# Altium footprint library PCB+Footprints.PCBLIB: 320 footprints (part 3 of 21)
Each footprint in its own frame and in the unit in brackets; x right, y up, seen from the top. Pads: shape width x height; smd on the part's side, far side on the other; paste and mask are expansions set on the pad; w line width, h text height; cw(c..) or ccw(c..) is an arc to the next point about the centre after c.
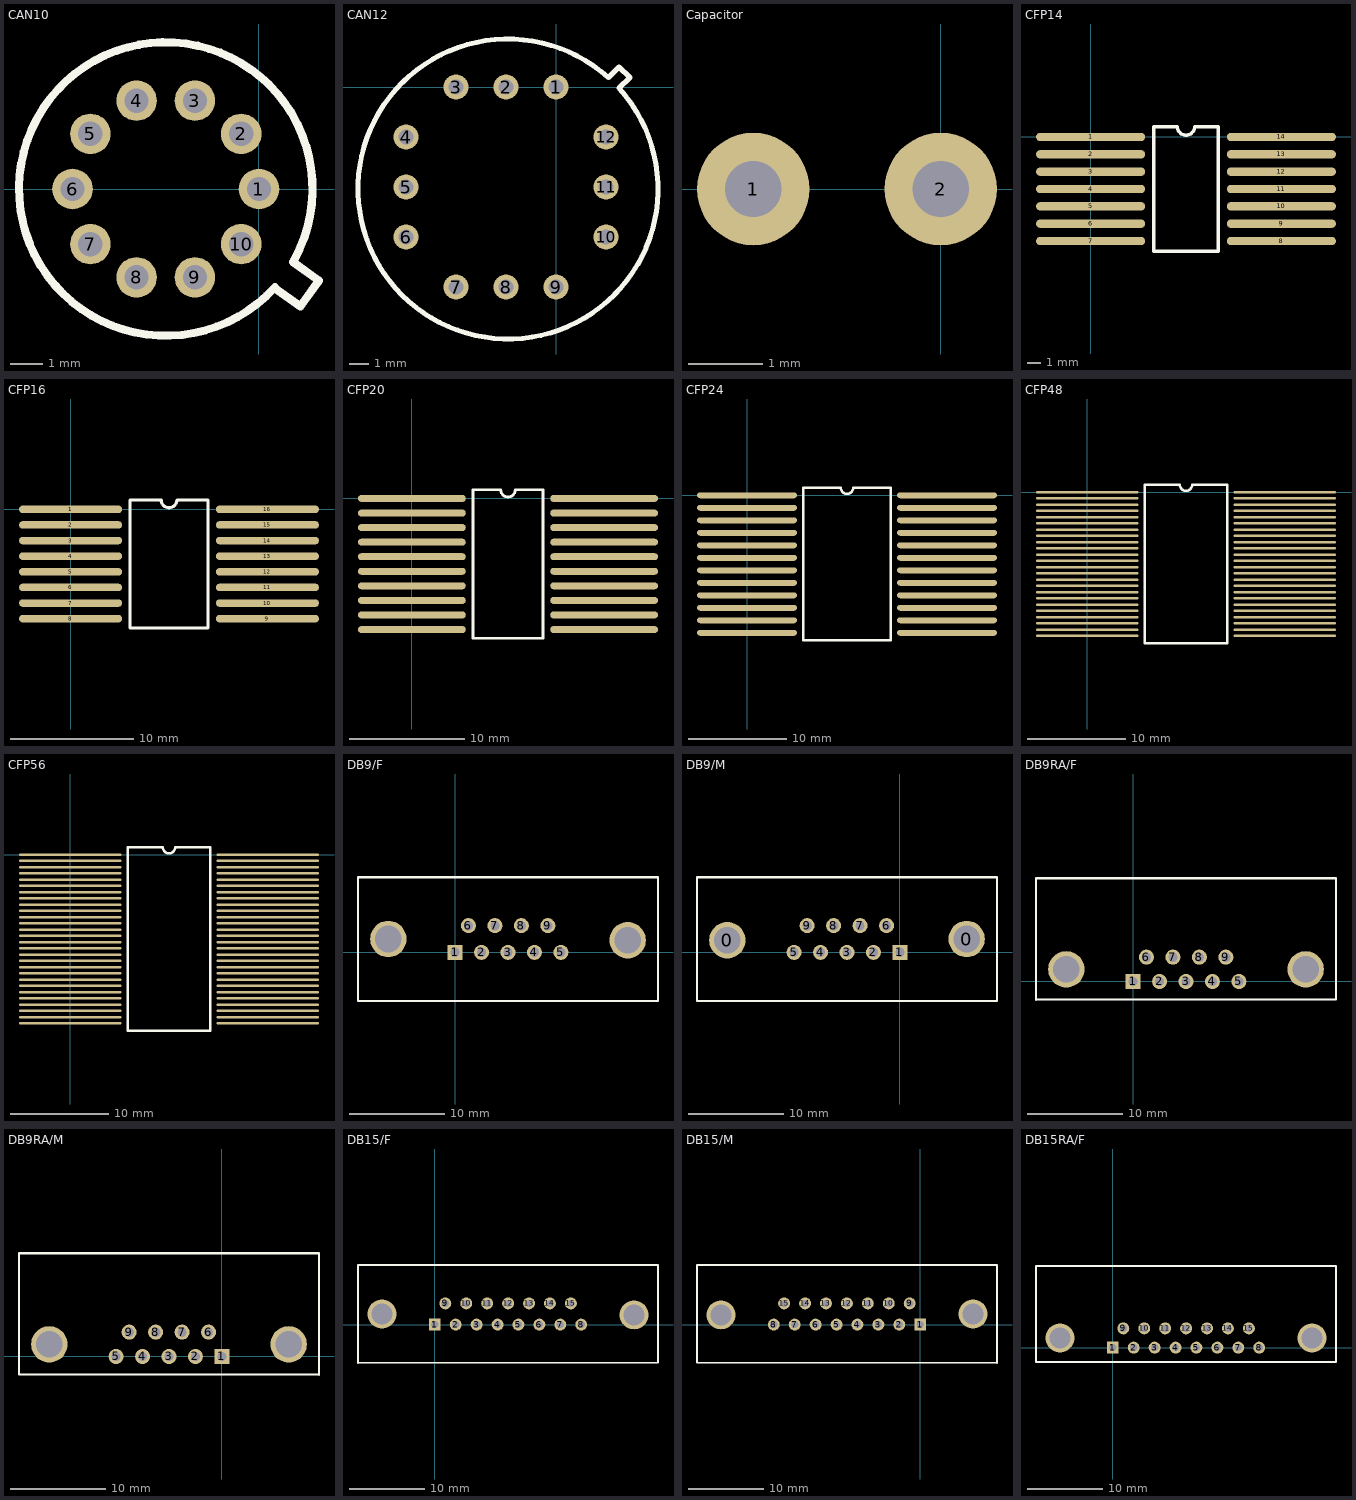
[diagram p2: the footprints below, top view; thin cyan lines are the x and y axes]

## CAN10 [mil]
pads (10):
  round 50 hole 30: 1(0,0) 2(-22,68) 3(-79,109) 4(-151,109) 5(-208,68) 6(-230,0) 7(-208,-68) 8(-151,-109) 9(-79,-109) 10(-22,-68)
TopOverlay:
  lines w10: 19,-122 51,-145 74,-113 42,-90 ; 19.51,-121.11 cw(c-115,0) 43.31,-87.75

## CAN12 [mil]
pads (12):
  round 50 hole 30: 1(0,0) 2(-100,0) 3(-200,0) 4(-300,-100) 5(-300,-200) 6(-300,-300) 7(-200,-400) 8(-100,-400) 9(0,-400) 10(100,-300) 11(100,-200) 12(100,-100)
TopOverlay:
  lines w10: 104.74,18.94 ccw(c-96,-204) 126.94,-3.26 ; 105,19 126,40 148,19 126,-2

## Capacitor [mil]
pads (2):
  round 60 hole 30: 1(-100,0) 2(0,0)
MultiLayer:
  lines w10: -100,-50 0,-50 ; -100,50 0,50

## CFP14 [mil]
pads (14):
  oval 315x24 smd: 1(0,0) 2(0,-50) 3(0,-100) 4(0,-150) 5(0,-200) 6(0,-250) 7(0,-300) 8(550,-300) 9(550,-250) 10(550,-200) 11(550,-150) 12(550,-100) 13(550,-50) 14(550,0)
TopOverlay:
  lines w10: 182,-330 368,-330 368,30 300,30 cw(c275,30) 250,30 182,30 182,-330

## CFP16 [mil]
pads (16):
  oval 330x24 smd: 1(0,0) 2(0,-50) 3(0,-100) 4(0,-150) 5(0,-200) 6(0,-250) 7(0,-300) 8(0,-350) 9(630,-350) 10(630,-300) 11(630,-250) 12(630,-200) 13(630,-150) 14(630,-100) 15(630,-50) 16(630,0)
TopOverlay:
  lines w10: 190,-380 190,30 290,30 ccw(c315,30) 340,30 440,30 440,-380 190,-380

## CFP20 [mil]
pads (20):
  oval 370x24 smd: 1(0,0) 2(0,-50) 3(0,-100) 4(0,-150) 5(0,-200) 6(0,-250) 7(0,-300) 8(0,-350) 9(0,-400) 10(0,-450) 11(660,-450) 12(660,-400) 13(660,-350) 14(660,-300) 15(660,-250) 16(660,-200) 17(660,-150) 18(660,-100) 19(660,-50) 20(660,0)
TopOverlay:
  lines w10: 210,30 210,30 ; 210,30 210,-480 450,-480 450,30 355,30 cw(c330,30) 305,30 210,30

## CFP24 [mil]
pads (24):
  oval 400x24 smd: 1(0,0) 2(0,-50) 3(0,-100) 4(0,-150) 5(0,-200) 6(0,-250) 7(0,-300) 8(0,-350) 9(0,-400) 10(0,-450) 11(0,-500) 12(0,-550) 13(800,-550) 14(800,-500) 15(800,-450) 16(800,-400) 17(800,-350) 18(800,-300) 19(800,-250) 20(800,-200) 21(800,-150) 22(800,-100) 23(800,-50) 24(800,0)
TopOverlay:
  lines w10: 225,-580 575,-580 575,30 425,30 cw(c400,30) 375,30 225,30 225,-580

## CFP48 [mil]
pads (48):
  oval 410x10 smd: 1(0,0) 2(0,-25) 3(0,-50) 4(0,-75) 5(0,-100) 6(0,-125) 7(0,-150) 8(0,-175) 9(0,-200) 10(0,-225) 11(0,-250) 12(0,-275) 13(0,-300) 14(0,-325) 15(0,-350) 16(0,-375) 17(0,-400) 18(0,-425) 19(0,-450) 20(0,-475) 21(0,-500) 22(0,-525) 23(0,-550) 24(0,-575) 25(790,-575) 26(790,-550) 27(790,-525) 28(790,-500) 29(790,-475) 30(790,-450) 31(790,-425) 32(790,-400) 33(790,-375) 34(790,-350) 35(790,-325) 36(790,-300) 37(790,-275) 38(790,-250) 39(790,-225) 40(790,-200) 41(790,-175) 42(790,-150) 43(790,-125) 44(790,-100) 45(790,-75) 46(790,-50) 47(790,-25) 48(790,0)
TopOverlay:
  lines w10: 230,30 230,30 ; 230,30 230,-605 560,-605 560,30 420,30 cw(c395,30) 370,30 230,30

## CFP56 [mil]
pads (56):
  oval 410x10 smd: 1(0,0) 2(0,-25) 3(0,-50) 4(0,-75) 5(0,-100) 6(0,-125) 7(0,-150) 8(0,-175) 9(0,-200) 10(0,-225) 11(0,-250) 12(0,-275) 13(0,-300) 14(0,-325) 15(0,-350) 16(0,-375) 17(0,-400) 18(0,-425) 19(0,-450) 20(0,-475) 21(0,-500) 22(0,-525) 23(0,-550) 24(0,-575) 25(0,-600) 26(0,-625) 27(0,-650) 28(0,-675) 29(790,-675) 30(790,-650) 31(790,-625) 32(790,-600) 33(790,-575) 34(790,-550) 35(790,-525) 36(790,-500) 37(790,-475) 38(790,-450) 39(790,-425) 40(790,-400) 41(790,-375) 42(790,-350) 43(790,-325) 44(790,-300) 45(790,-275) 46(790,-250) 47(790,-225) 48(790,-200) 49(790,-175) 50(790,-150) 51(790,-125) 52(790,-100) 53(790,-75) 54(790,-50) 55(790,-25) 56(790,0)
TopOverlay:
  lines w10: 230,30 230,30 ; 230,30 230,-705 560,-705 560,30 420,30 cw(c395,30) 370,30 230,30

## DB9/F [mil]
pads (11):
  rect 62x62 hole 38: 1(0,0)
  round 62 hole 38: 2(109,0) 3(218,0) 4(327,0) 5(436,0) 6(55,110) 7(164,110) 8(273,110) 9(382,110)
  round 150 hole 110: ""(-275,55) ""(711,50)
TopOverlay:
  lines w8: -400,-200 836,-200 836,310
  lines w10: -400,-200 -400,310 836,310

## DB9/M [mil]
pads (11):
  round 150 hole 110: 0(-711,50) 0(275,55)
  rect 62x62 hole 38: 1(0,0)
  round 62 hole 38: 2(-109,0) 3(-218,0) 4(-327,0) 5(-436,0) 6(-55,110) 7(-164,110) 8(-273,110) 9(-382,110)
TopOverlay:
  lines w8: -836,310 -836,-200 400,-200
  lines w10: -836,310 400,310 400,-200

## DB9RA/F [mil]
pads (11):
  rect 62x62 hole 38: 1(0,0)
  round 62 hole 38: 2(109,0) 3(218,0) 4(327,0) 5(436,0) 6(55,100) 7(164,100) 8(273,100) 9(382,100)
  round 150 hole 110: ""(-275,50) ""(711,50)
TopOverlay:
  lines w8: -400,-75 836,-75 836,425
  lines w10: -400,-75 -400,425 836,425

## DB9RA/M [mil]
pads (11):
  rect 62x62 hole 38: 1(0,0)
  round 62 hole 38: 2(-109,0) 3(-218,0) 4(-327,0) 5(-436,0) 6(-55,100) 7(-164,100) 8(-273,100) 9(-382,100)
  round 150 hole 110: ""(-711,50) ""(275,50)
TopOverlay:
  lines w8: -836,425 -836,-75 400,-75
  lines w10: -836,425 400,425 400,-75

## DB15/F [mil]
pads (17):
  rect 62x62 hole 38: 1(0,0)
  round 62 hole 38: 2(109,0) 3(218,0) 4(327,0) 5(436,0) 6(545,0) 7(654,0) 8(763,0) 9(55,110) 10(164,110) 11(273,110) 12(382,110) 13(491,110) 14(600,110) 15(709,110)
  round 150 hole 110: ""(-275,55) ""(1038,50)
TopOverlay:
  lines w8: -400,-200 1163,-200 1163,310
  lines w10: -400,-200 -400,310 1163,310

## DB15/M [mil]
pads (17):
  rect 62x62 hole 38: 1(0,0)
  round 62 hole 38: 2(-109,0) 3(-218,0) 4(-327,0) 5(-436,0) 6(-545,0) 7(-654,0) 8(-763,0) 9(-55,110) 10(-164,110) 11(-273,110) 12(-382,110) 13(-491,110) 14(-600,110) 15(-709,110)
  round 150 hole 110: ""(-1038,50) ""(275,55)
TopOverlay:
  lines w8: -1163,310 -1163,-200 400,-200
  lines w10: -1163,310 400,310 400,-200

## DB15RA/F [mil]
pads (17):
  rect 62x62 hole 38: 1(0,0)
  round 62 hole 38: 2(109,0) 3(218,0) 4(327,0) 5(436,0) 6(545,0) 7(654,0) 8(763,0) 9(55,100) 10(164,100) 11(273,100) 12(382,100) 13(491,100) 14(600,100) 15(709,100)
  round 150 hole 110: ""(-275,50) ""(1038,50)
TopOverlay:
  lines w8: -400,-75 1163,-75 1163,425
  lines w10: -400,-75 -400,425 1163,425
